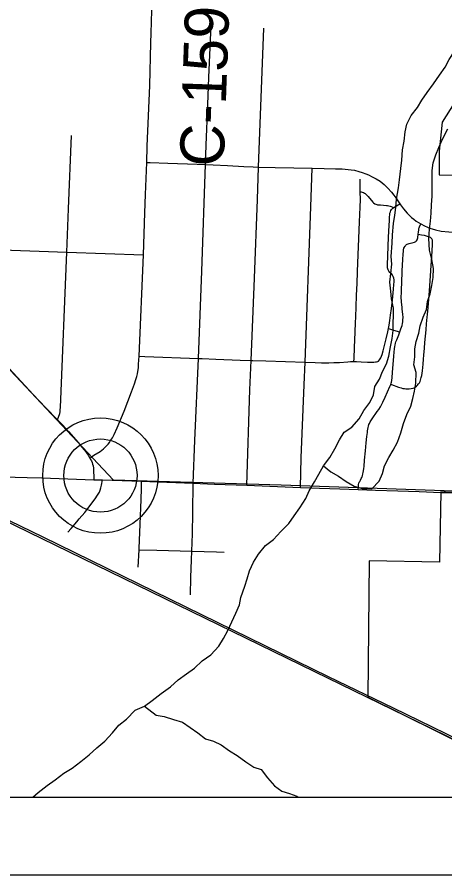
# Model space of a CAD drawing. Extents: x 0 to 34, y 0 to 22.
# Drawn here: x 6.327 to 6.879, y 14 to 15.105 of the extents above; entities that cross this region are included whole.
import ezdxf

# ---------------------------------------------------------------- set-up
doc = ezdxf.new("R2010")
doc.units = 0
for name, color, linetype in [('GM_X_Corporation', 7, 'Continuous'), ('GM_X_County_Road', 7, 'Continuous'), ('GM_X_County_Road_Text', 7, 'Continuous'), ('GM_X_Minor_River', 7, 'Continuous'), ('GM_X_Rail_Line', 7, 'Continuous'), ('GM_X_State_Route', 7, 'Continuous'), ('GM_X_Township_Road', 7, 'Continuous'), ('GM_X_Unincorporated', 7, 'Continuous'), ('GM_X_Unincorporated_Location', 7, 'Continuous'), ('SH_Data', 7, 'Continuous')]:
    doc.layers.add(name, color=color, linetype=linetype)

msp = doc.modelspace()

# ---------------------------------------------------------------- linework, layer by layer
at = {"layer": 'GM_X_Corporation'}
for points in [[(5.0288, 16.3849), (5.0353, 14.97), (5.0366, 14.7668), (5.0395, 14.6051), (5.0378, 14.5635), (5.0381, 14.4922), (5.0411, 14.425), (5.0398, 14.1), (8.9, 14.1)], [(6.9525, 15.1334), (6.9503, 15.0249), (6.917, 15.0125), (6.8908, 14.9944), (6.8752, 14.9702), (6.8714, 14.9326), (6.8717, 14.9023), (6.9429, 14.9009), (6.9484, 14.8268), (6.9429, 14.7155), (6.9388, 14.604), (6.9341, 14.4915), (6.9291, 14.4917), (6.9179, 14.492), (6.9005, 14.4926), (6.8932, 14.4928), (6.8796, 14.4932), (6.8735, 14.4935), (6.8719, 14.4029), (6.7813, 14.4049), (6.7796, 14.2289), (6.9139, 14.1625), (6.9117, 14.1), (8.9, 14.1)]]:
    msp.add_lwpolyline(points, dxfattribs=at)
at = {"layer": 'GM_X_County_Road'}
msp.add_line((6.4846, 14.6683), (6.4902, 14.799), dxfattribs=at)
for points in [[(6.4945, 14.9182), (6.4951, 14.939), (6.4982, 15.0173), (6.4998, 15.0723), (6.5001, 15.0848), (6.5009, 15.114), (6.5011, 15.1192)], [(6.4902, 14.799), (6.492, 14.8533), (6.4929, 14.8768), (6.4945, 14.9182)], [(6.2968, 14.6742), (6.322, 14.647), (6.348, 14.619), (6.3644, 14.602), (6.3793, 14.5865)], [(6.4209, 14.5372), (6.4263, 14.5407), (6.4342, 14.5458), (6.4365, 14.5474), (6.4385, 14.5491), (6.4416, 14.552), (6.4446, 14.5552), (6.4463, 14.5573), (6.4479, 14.5597), (6.4501, 14.5633), (6.4524, 14.5674), (6.4561, 14.5759), (6.4651, 14.5977), (6.4749, 14.6225), (6.4788, 14.633), (6.4805, 14.6383), (6.4816, 14.6422), (6.4824, 14.6458), (6.483, 14.6488), (6.4836, 14.6536), (6.484, 14.6581), (6.4846, 14.6683)], [(6.3793, 14.5865), (6.3862, 14.5794), (6.3935, 14.5715), (6.4058, 14.5574), (6.4065, 14.5566)], [(6.4065, 14.5566), (6.4105, 14.5518), (6.4144, 14.5468), (6.4188, 14.5407), (6.4209, 14.5372)], [(6.4209, 14.5372), (6.4221, 14.5354), (6.4231, 14.5335), (6.4239, 14.5313), (6.4246, 14.5293), (6.4252, 14.527), (6.4256, 14.5241), (6.4264, 14.5093)]]:
    msp.add_lwpolyline(points, dxfattribs=at)
at = {"layer": 'GM_X_Minor_River'}
for points in [[(6.8434, 14.989), (6.8491, 14.9985), (6.8562, 15.0081), (6.8644, 15.0195), (6.8719, 15.0306), (6.8794, 15.0409), (6.8846, 15.0508), (6.891, 15.0607), (6.8985, 15.0706), (6.9172, 15.0897), (6.9202, 15.0935)], [(6.3476, 14.1), (6.3545, 14.1061), (6.3661, 14.1153), (6.3763, 14.1226), (6.3876, 14.131), (6.3981, 14.1376), (6.4094, 14.146), (6.4203, 14.1548), (6.4301, 14.1636), (6.4402, 14.1724), (6.4504, 14.1831), (6.4586, 14.1927), (6.4684, 14.2007), (6.4793, 14.2122), (6.4914, 14.2176), (6.5015, 14.2248), (6.5132, 14.2337), (6.5252, 14.2421), (6.535, 14.2513), (6.5459, 14.2589), (6.5561, 14.2662), (6.5659, 14.2758), (6.5771, 14.2834), (6.5873, 14.2949), (6.5936, 14.3048), (6.5992, 14.3151), (6.6041, 14.3261), (6.6093, 14.3372), (6.6141, 14.3478), (6.6156, 14.3573), (6.6211, 14.3722), (6.6241, 14.3817), (6.627, 14.3919), (6.6322, 14.403), (6.6386, 14.4132), (6.6476, 14.4243), (6.6577, 14.4324), (6.6675, 14.4427), (6.6777, 14.453), (6.6844, 14.4625), (6.6919, 14.4732), (6.6997, 14.485), (6.7038, 14.4949), (6.7109, 14.5067), (6.7165, 14.5166), (6.7225, 14.5273), (6.7307, 14.538), (6.7371, 14.549), (6.7431, 14.5608), (6.749, 14.5707), (6.7588, 14.5769), (6.7682, 14.5876), (6.7742, 14.5986), (6.782, 14.6089), (6.7869, 14.6188), (6.7887, 14.6294), (6.7947, 14.639), (6.7984, 14.6489), (6.8036, 14.6584), (6.8066, 14.6683), (6.8087, 14.6804), (6.8109, 14.6914), (6.812, 14.7017), (6.8123, 14.7112), (6.8126, 14.721), (6.8125, 14.7305), (6.8102, 14.7423), (6.8093, 14.7521), (6.8077, 14.7638), (6.8091, 14.7752), (6.8106, 14.787), (6.8097, 14.7969), (6.8107, 14.8139), (6.8114, 14.8249), (6.8128, 14.8394), (6.8142, 14.85), (6.8157, 14.8599), (6.8164, 14.8709), (6.8189, 14.8853), (6.8203, 14.8959), (6.8221, 14.9104), (6.8232, 14.921), (6.8242, 14.9346), (6.8264, 14.9457), (6.8278, 14.9574), (6.83, 14.9673), (6.8356, 14.9787), (6.8434, 14.989)], [(6.7225, 14.5273), (6.732, 14.5194), (6.7419, 14.5138), (6.7514, 14.507), (6.7621, 14.501), (6.7723, 14.4981), (6.7848, 14.4974), (6.7942, 14.5074), (6.7986, 14.5173), (6.8012, 14.5271), (6.8068, 14.5378), (6.812, 14.5473), (6.8176, 14.5576), (6.8221, 14.5698), (6.8254, 14.5819), (6.8298, 14.5933), (6.8351, 14.604), (6.8376, 14.6139), (6.8398, 14.6234), (6.8413, 14.6336), (6.8419, 14.6473), (6.8388, 14.6571), (6.8403, 14.6678), (6.8402, 14.678), (6.842, 14.6875), (6.8453, 14.6981), (6.8471, 14.7076), (6.8508, 14.7187), (6.8553, 14.7286), (6.8564, 14.7388), (6.8597, 14.7487), (6.8619, 14.7597), (6.8637, 14.77), (6.864, 14.7813), (6.862, 14.7931), (6.8589, 14.8052), (6.858, 14.82), (6.859, 14.8321), (6.8605, 14.8424), (6.8612, 14.8526), (6.8618, 14.8633), (6.8625, 14.8746), (6.8623, 14.8981), (6.8626, 14.9076), (6.8637, 14.9175), (6.8674, 14.9278), (6.8711, 14.9373), (6.8756, 14.9483), (6.8826, 14.9613)], [(6.4914, 14.2176), (6.5066, 14.2059), (6.5168, 14.2041), (6.529, 14.2), (6.5407, 14.1967), (6.5506, 14.1899), (6.5601, 14.1832), (6.5704, 14.1753), (6.5803, 14.1723), (6.5902, 14.1675), (6.6012, 14.16), (6.6111, 14.1536), (6.6221, 14.1457), (6.6324, 14.1386), (6.6419, 14.1356), (6.6503, 14.1251), (6.6591, 14.1149), (6.6686, 14.1078), (6.6784, 14.1048), (6.6879, 14.1015), (6.6897, 14.1)]]:
    msp.add_lwpolyline(points, dxfattribs=at)
at = {"layer": 'GM_X_Rail_Line'}
for points in [[(6.8127, 14.2147), (6.7289, 14.2554), (6.3608, 14.435), (6.2746, 14.4768), (5.684, 14.7652), (5.3068, 14.9483), (5.2824, 14.9601), (4.9789, 15.1067), (4.4214, 15.3767)], [(6.8117, 14.2126), (6.7279, 14.2533), (6.3597, 14.4329), (6.2736, 14.4747), (5.6829, 14.7631), (5.3058, 14.9462), (5.2814, 14.958), (4.9779, 15.1046), (4.4205, 15.3745)], [(7.7906, 14.1), (7.7891, 14.1611), (7.792, 14.368), (7.7915, 14.4601), (7.677, 14.4615), (7.605, 14.4663), (7.4966, 14.4734), (7.0511, 14.4887), (6.6677, 14.502), (6.4516, 14.5087), (6.0517, 14.9336), (5.3617, 14.959), (5.2822, 14.9606)], [(7.0431, 14.1), (6.9299, 14.1551), (6.8117, 14.2126)], [(7.0484, 14.1), (6.931, 14.1572), (6.8127, 14.2147)]]:
    msp.add_lwpolyline(points, dxfattribs=at)
at = {"layer": 'GM_X_State_Route'}
for points in [[(6.1622, 14.5172), (6.2468, 14.5145), (6.3401, 14.512)], [(6.3401, 14.512), (6.3592, 14.5115), (6.4264, 14.5093), (6.4375, 14.5089), (6.4878, 14.5072), (6.509, 14.5065)], [(6.509, 14.5065), (6.5544, 14.5049), (6.5817, 14.5037), (6.6235, 14.5023), (6.6927, 14.4994), (6.7171, 14.4984), (6.7435, 14.4974), (6.7672, 14.4966), (6.7894, 14.4959), (6.8183, 14.4949), (6.8457, 14.4939), (6.8737, 14.4929)], [(6.8737, 14.4929), (6.8798, 14.4927), (6.8934, 14.4922), (6.9007, 14.492), (6.9181, 14.4915), (6.9293, 14.4911), (6.9343, 14.4909)]]:
    msp.add_lwpolyline(points, dxfattribs=at)
at = {"layer": 'GM_X_Township_Road'}
for p, q in [((6.6386, 14.9121), (6.6453, 15.0914)), ((6.3915, 14.8024), (6.4902, 14.799)), ((6.4834, 14.3966), (6.4846, 14.4188))]:
    msp.add_line(p, q, dxfattribs=at)
for points in [[(6.57, 14.9154), (6.5709, 14.9402), (6.5731, 14.9929), (6.5746, 15.0276), (6.5777, 15.095)], [(6.3915, 14.8024), (6.3937, 14.8583), (6.3974, 14.9527)], [(6.4945, 14.9182), (6.499, 14.9181), (6.5216, 14.9172), (6.5595, 14.9158), (6.57, 14.9154)], [(6.5611, 14.6655), (6.5655, 14.778), (6.57, 14.9154)], [(6.57, 14.9154), (6.5799, 14.915), (6.5986, 14.9142), (6.6197, 14.913), (6.6318, 14.9124), (6.6386, 14.9121)], [(6.629, 14.663), (6.6335, 14.769), (6.6371, 14.8702), (6.6386, 14.9121)], [(6.6386, 14.9121), (6.6601, 14.9116), (6.6842, 14.9111), (6.7079, 14.9107)], [(6.6986, 14.6606), (6.706, 14.861), (6.7079, 14.9107)], [(6.7079, 14.9107), (6.7234, 14.9103), (6.7379, 14.91), (6.7463, 14.9097), (6.7543, 14.9092), (6.7582, 14.9087), (6.7622, 14.908), (6.7681, 14.9065), (6.7724, 14.9052), (6.7768, 14.9036), (6.7804, 14.9021), (6.785, 14.8998), (6.7901, 14.8971), (6.7953, 14.8938), (6.8006, 14.8897), (6.8055, 14.8851), (6.81, 14.88), (6.8129, 14.8761), (6.8155, 14.8726), (6.8208, 14.8649)], [(6.7615, 14.6614), (6.7617, 14.6655), (6.7625, 14.6798), (6.7633, 14.6996), (6.7637, 14.712), (6.764, 14.7188), (6.7651, 14.7461), (6.7655, 14.7554), (6.7657, 14.7616), (6.7663, 14.7777), (6.7689, 14.8417), (6.7697, 14.8603), (6.7699, 14.8702), (6.7697, 14.8804), (6.7696, 14.8906), (6.7695, 14.8967)], [(6.7697, 14.8804), (6.771, 14.8801), (6.7724, 14.8797), (6.7738, 14.8792), (6.7751, 14.8786), (6.7763, 14.8779), (6.7774, 14.8769), (6.7787, 14.8757), (6.78, 14.8742), (6.7816, 14.8723), (6.7841, 14.8693), (6.7859, 14.8671), (6.787, 14.8659), (6.7884, 14.8649), (6.7897, 14.8643), (6.791, 14.8638), (6.7918, 14.8637), (6.7929, 14.8635), (6.7957, 14.8633), (6.8034, 14.8627), (6.805, 14.8625), (6.8066, 14.8622), (6.8085, 14.8616), (6.8129, 14.8599)], [(6.7934, 14.6622), (6.7946, 14.6637), (6.7956, 14.6651), (6.7964, 14.6665), (6.7971, 14.6683), (6.7978, 14.6705), (6.7991, 14.6754), (6.8031, 14.6909), (6.8054, 14.7), (6.8063, 14.704), (6.807, 14.7086), (6.808, 14.7146), (6.8089, 14.7211), (6.81, 14.7301), (6.8112, 14.7405), (6.8126, 14.7549), (6.8131, 14.7609), (6.8133, 14.7644), (6.8133, 14.7667), (6.8129, 14.769), (6.8122, 14.771), (6.8114, 14.7728), (6.8103, 14.7743), (6.8081, 14.7765), (6.8068, 14.778), (6.8058, 14.7797), (6.805, 14.7821), (6.8049, 14.7839), (6.8049, 14.7861), (6.8063, 14.8219), (6.807, 14.837), (6.8073, 14.8434), (6.8075, 14.8479), (6.8078, 14.8505), (6.8081, 14.8528), (6.8086, 14.8545), (6.8092, 14.8561), (6.8101, 14.8574), (6.811, 14.8584), (6.8117, 14.8591), (6.8129, 14.8599), (6.8163, 14.8621), (6.8208, 14.8649)], [(6.8208, 14.8649), (6.8218, 14.8634), (6.8255, 14.8584), (6.8303, 14.8527), (6.8332, 14.8496), (6.836, 14.8472), (6.8387, 14.8451), (6.842, 14.8426), (6.845, 14.8406), (6.8478, 14.8389)], [(6.7672, 14.4966), (6.7672, 14.4973), (6.7673, 14.4993), (6.7674, 14.5014), (6.7676, 14.5029), (6.768, 14.5046), (6.7685, 14.5059), (6.769, 14.5071), (6.77, 14.5088), (6.7709, 14.5106), (6.7716, 14.512), (6.7721, 14.5132), (6.7725, 14.5144), (6.7731, 14.5167), (6.7736, 14.5184), (6.774, 14.5205), (6.7744, 14.5236), (6.7747, 14.5263), (6.7754, 14.5343), (6.7764, 14.5466), (6.7774, 14.5569), (6.7783, 14.5649), (6.7789, 14.57), (6.7791, 14.5724), (6.7795, 14.5746), (6.7798, 14.5766), (6.7803, 14.5783), (6.7809, 14.5803), (6.7815, 14.5819), (6.7824, 14.5837), (6.7833, 14.5853), (6.7867, 14.5903), (6.7899, 14.5945), (6.7917, 14.5971), (6.7936, 14.5998), (6.7957, 14.6031), (6.7972, 14.6059), (6.7989, 14.6093), (6.8019, 14.6158), (6.808, 14.6293), (6.8092, 14.6321), (6.8096, 14.6335), (6.8099, 14.635), (6.8103, 14.6371), (6.8107, 14.6411), (6.8112, 14.6473), (6.8129, 14.6685), (6.8134, 14.6737), (6.8139, 14.678), (6.8143, 14.6809), (6.8146, 14.6827), (6.8152, 14.6853), (6.8158, 14.6871), (6.8168, 14.6897), (6.8194, 14.6961), (6.8209, 14.6998), (6.8221, 14.7035), (6.8236, 14.7079), (6.8242, 14.7104), (6.8246, 14.7127), (6.8248, 14.7151), (6.8249, 14.7181), (6.8245, 14.7228), (6.8239, 14.7289), (6.8236, 14.7313), (6.823, 14.7387), (6.8227, 14.7448), (6.8228, 14.7503), (6.823, 14.7552), (6.8232, 14.7624), (6.8238, 14.7784), (6.8246, 14.7932), (6.8252, 14.8), (6.8255, 14.8036), (6.8257, 14.8057), (6.8261, 14.8075), (6.8266, 14.8088), (6.8273, 14.8101), (6.8279, 14.8108), (6.8284, 14.8114), (6.8293, 14.8122), (6.8301, 14.8126), (6.8314, 14.8132), (6.8327, 14.8135), (6.8346, 14.814), (6.8368, 14.8145), (6.8396, 14.8154), (6.8406, 14.8158), (6.8415, 14.8164), (6.8422, 14.8172), (6.843, 14.8184), (6.8435, 14.8198), (6.8439, 14.8211), (6.8442, 14.8223), (6.8444, 14.8242), (6.8446, 14.8254), (6.8449, 14.8288), (6.8451, 14.8307), (6.8452, 14.8321), (6.8454, 14.8331), (6.8456, 14.8338), (6.846, 14.8352), (6.8478, 14.8389)], [(6.8478, 14.8389), (6.8527, 14.8364), (6.8563, 14.8348), (6.8596, 14.8335), (6.8668, 14.8313), (6.8741, 14.8297), (6.8838, 14.8285), (6.8995, 14.8277), (6.9166, 14.8273)], [(6.8092, 14.6321), (6.81, 14.6318), (6.8189, 14.6286), (6.8224, 14.6275), (6.8246, 14.6269), (6.8268, 14.6266), (6.8287, 14.6264), (6.8309, 14.6262), (6.8327, 14.6263), (6.8353, 14.6266), (6.838, 14.6273), (6.8402, 14.6283), (6.8421, 14.6296), (6.8432, 14.6306), (6.8449, 14.6326), (6.846, 14.6343), (6.8468, 14.6359), (6.8474, 14.6376), (6.8479, 14.6391), (6.8484, 14.6408), (6.8491, 14.6435), (6.8495, 14.6464), (6.85, 14.6497), (6.8505, 14.6539), (6.851, 14.6583), (6.8515, 14.6646), (6.8519, 14.6699), (6.8526, 14.6788), (6.8532, 14.6859), (6.854, 14.6944), (6.8547, 14.7026), (6.8553, 14.7103), (6.856, 14.7186), (6.8563, 14.7221), (6.8572, 14.731), (6.859, 14.7525), (6.8604, 14.7718), (6.8613, 14.7853), (6.862, 14.7967), (6.863, 14.8123), (6.8631, 14.8147), (6.8631, 14.8158), (6.863, 14.8167), (6.8628, 14.8179), (6.8624, 14.8189), (6.862, 14.8196), (6.8614, 14.8204), (6.8608, 14.821), (6.8602, 14.8214), (6.8596, 14.8218), (6.8584, 14.8224), (6.8566, 14.8229), (6.8525, 14.8238), (6.8486, 14.8246), (6.8446, 14.8254)], [(6.304, 14.8056), (6.3081, 14.8055), (6.3915, 14.8024)], [(6.3793, 14.5865), (6.3811, 14.5911), (6.3819, 14.5933), (6.3822, 14.5946), (6.3826, 14.5966), (6.3827, 14.5977), (6.3829, 14.5995), (6.3831, 14.6023), (6.3915, 14.8024)], [(6.8063, 14.704), (6.8102, 14.7028), (6.8157, 14.7013), (6.8202, 14.7), (6.8209, 14.6998)], [(6.4846, 14.6683), (6.4919, 14.668), (6.5611, 14.6655)], [(6.5544, 14.5049), (6.5566, 14.5596), (6.5611, 14.6655)], [(6.5611, 14.6655), (6.566, 14.6653), (6.5834, 14.6646), (6.6151, 14.6635), (6.629, 14.663)], [(6.6235, 14.5023), (6.6274, 14.625), (6.629, 14.663)], [(6.629, 14.663), (6.6313, 14.6629), (6.648, 14.6623), (6.6986, 14.6606)], [(6.6927, 14.4994), (6.6935, 14.5373), (6.6975, 14.6315), (6.6986, 14.6606)], [(6.6986, 14.6606), (6.7117, 14.6602), (6.7196, 14.66), (6.725, 14.6599), (6.7292, 14.6599), (6.7356, 14.6601), (6.7428, 14.6602)], [(6.7428, 14.6602), (6.7539, 14.6611), (6.7571, 14.6614), (6.7598, 14.6615), (6.7615, 14.6614), (6.7651, 14.6614), (6.7711, 14.6612), (6.7792, 14.6609), (6.785, 14.6609), (6.7873, 14.6609), (6.7894, 14.661), (6.7909, 14.6612), (6.7923, 14.6617), (6.7934, 14.6622)], [(6.3927, 14.4418), (6.3968, 14.4464), (6.4041, 14.4551), (6.4073, 14.4589), (6.4144, 14.4672), (6.4185, 14.4722), (6.4279, 14.4846), (6.4311, 14.4893), (6.4333, 14.4931), (6.4344, 14.4958), (6.4353, 14.4989), (6.4362, 14.5024), (6.4375, 14.5089)], [(6.4846, 14.4188), (6.4847, 14.4204), (6.4861, 14.452), (6.4872, 14.4837), (6.4876, 14.498), (6.4878, 14.5072)], [(6.5525, 14.4173), (6.5533, 14.4396), (6.5538, 14.4671), (6.5544, 14.5049)], [(6.4846, 14.4188), (6.5073, 14.4183), (6.5525, 14.4173)], [(6.5507, 14.3608), (6.5514, 14.3833), (6.5522, 14.4058), (6.5525, 14.4173)], [(6.5525, 14.4173), (6.5684, 14.4169), (6.5844, 14.4163), (6.5943, 14.4159)]]:
    msp.add_lwpolyline(points, dxfattribs=at)
at = {"layer": 'GM_X_Unincorporated'}
for radius in [0.0744, 0.0472]:
    msp.add_circle((6.4347, 14.5146), radius, dxfattribs=at)
at = {"layer": 'GM_X_Unincorporated_Location'}
msp.add_line((6.4347, 14.5146), (6.4347, 14.5146), dxfattribs=at)
at = {"layer": 'SH_Data'}
for p, q in [((2.1, 14.1), (8.9, 14.1)), ((2, 14), (9, 14))]:
    msp.add_line(p, q, dxfattribs=at)

# ---------------------------------------------------------------- texts
at = {"layer": 'GM_X_County_Road_Text'}
msp.add_text('C-159', height=0.05682, rotation=87.9948, dxfattribs=at).set_placement((6.5936, 14.912))

doc.saveas('drawing.dxf')
